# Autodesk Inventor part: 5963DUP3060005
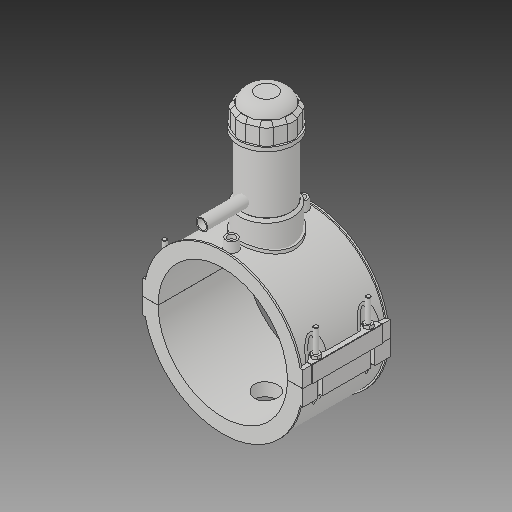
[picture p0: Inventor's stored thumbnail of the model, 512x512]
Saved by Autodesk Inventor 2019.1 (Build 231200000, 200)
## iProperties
Created: 2017-07
Part Number: 5963DUP3060005
Material: Generic
Description: PLASSON TAPPING SADDLE 6''DIPS x 1/2''CTS
Document SubType Name: Modeling
Designer: KIM
Density: 1 g/cm^3
Appearance: Default
Author: KIM
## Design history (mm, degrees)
derived "5963DBP_5963BUP.ipt"
feature "Solid1::5963DBP_5963BUP.ipt"
feature "Solid2::5963DBP_5963BUP.ipt"
feature "Solid3::5963DBP_5963BUP.ipt"
tag "TaggingFeature1"
body "Solid1"
body "Solid2"
body "Solid3"
other parameters: "d0" = 174.5, "d2" = 215.9, "d3" = 43.625, "d4" = 118.11, "d5" = 0, "d6" = 0.1, "d8" = 0, "d19" = 6, "d20" = 6, "d21" = 70.866, "d23" = 0, "d24" = 35.433, "d26" = 0, "d27" = 3, "d28" = 3, "d29" = 3, "d30" = 58.16667, "d31" = 6, "d32" = 0, "d33" = 0, "d34" = 0.6, "d40" = 108.888, "d41" = 75.035, "d43" = 0, "d45" = 0, "d47" = 175.566, "d70" = 15, "d72" = 0, "d73" = 6, "d75" = 5, "d76" = 0, "d77" = 8.725, "d78" = 117.25, "d79" = 15, "d80" = 47.244, "d82" = 5 deg, "d84" = 4, "d85" = 14, "d86" = 0, "d87" = 3, "d88" = 0, "d89" = 1, "d90" = 1, "d91" = 94.488, "d92" = 0, "d93" = 0.5, "d94" = 91.84211, "d96" = 213.588, "d97" = 2.3622, "d98" = 0, "d120" = 140 deg, "d121" = 24.228, "d122" = 20 deg, "d123" = 418.8, "d124" = 125.64, "d126" = 0, "d143" = 179.735, "d145" = 26.84615, "d149" = 2.6175, "d150" = 29.53077, "d153" = 118.11, "d154" = 0, "d156" = 104.7, "d157" = 160 deg, "d159" = 6.98, "d161" = 2.6175, "d162" = 70.866, "d163" = 0, "d164" = 87.25, "d167" = 17.45, "d168" = 102.14634, "d170" = 3.4335, "d172" = 0, "d173" = 1, "d175" = 87.25, "d176" = 20 deg, "d177" = 12.215, "d178" = 34.9, "d180" = 0, "d183" = 13.96, "d184" = 9.772, "d185" = 38.38575, "d186" = 38.38575, "d187" = 104.7, "d188" = 10.47, "d189" = 12.215, "d190" = 0, "d191" = 157.05, "d193" = 7.3248, "d194" = 4.13385, "d195" = 90 deg, "d197" = 0, "d199" = 0, "d200" = 17.45, "d202" = 0, "d203" = 177.038, "d204" = 71.28325, "d205" = 52.5245, "d206" = 63.77975, "d207" = 132.7785, "d208" = 138.08964, "d209" = 164.64534, "d210" = 64.5301, "d211" = 75.035, "d212" = 60.028, "d213" = 51.4116, "d216" = 0, "d217" = 17.45, "d218" = 17.45, "d219" = 3.49, "d222" = 174.5, "d224" = 0, "d225" = 65.024, "d226" = 15.8, "d227" = 12.64, "d228" = 87.376, "d230" = 5.235, "d_" = 174.5, "B_" = 215.9, "L_" = 118.11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
